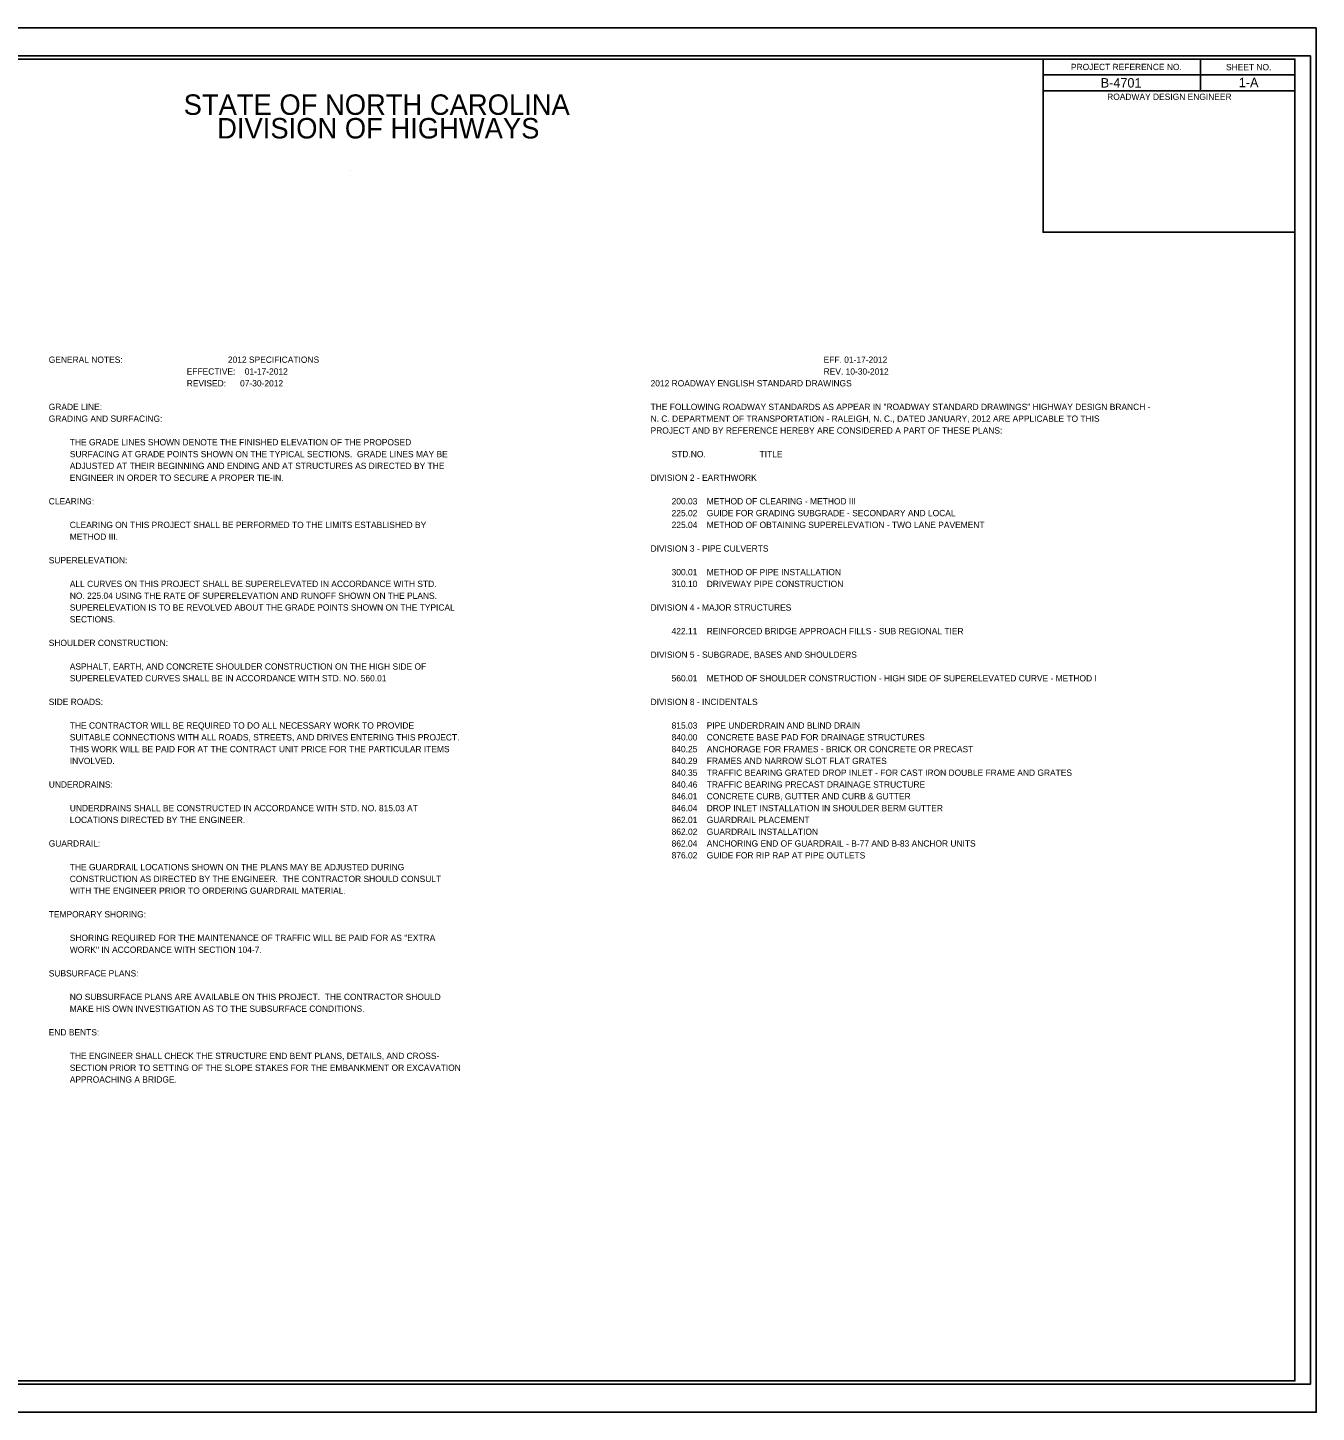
# Model space of a CAD drawing. Extents: x 573885.1 to 573944.9, y -53259.7 to -53181.6.
# Drawn here: x 573916.45 to 573936.92, y -53203.6 to -53181.6 of the extents above; entities that cross this region are included whole.
import ezdxf

# ---------------------------------------------------------------- set-up
doc = ezdxf.new("R2010")
doc.units = 0
for name, color, linetype in [('Default', 7, 'Continuous'), ('Sheet Border Standard 30in CELL', 7, 'Continuous'), ('Sheet Cutting Line CELL', 7, 'Continuous'), ('Sheet Data Field CELL', 7, 'Continuous'), ('Sheet Plot Border Inside CELL', 7, 'Continuous'), ('Sheet Plot Border Outside CELL', 7, 'Continuous'), ('Sheet Summary CELL', 7, 'Continuous')]:
    doc.layers.add(name, color=color, linetype=linetype)

msp = doc.modelspace()

# ---------------------------------------------------------------- linework, layer by layer
at = {"layer": 'Sheet Border Standard 30in CELL'}
msp.add_line((573936.579, -53182.604), (573936.579, -53184.853), dxfattribs=at)
msp.add_lwpolyline([(573932.578, -53182.604), (573936.579, -53182.604), (573936.579, -53184.854), (573932.578, -53184.854)], close=True, dxfattribs=at)
at = {"layer": 'Sheet Cutting Line CELL'}
for p, q in [((573936.919, -53181.603), (573903.239, -53181.603)), ((573903.239, -53203.603), (573936.919, -53203.603))]:
    msp.add_line(p, q, dxfattribs=at)
at = {"layer": 'Sheet Plot Border Inside CELL'}
msp.add_lwpolyline([(573936.829, -53182.052), (573903.499, -53182.052), (573903.499, -53203.154), (573936.829, -53203.154)], close=True, dxfattribs=at)
at = {"layer": 'Sheet Plot Border Outside CELL'}
msp.add_lwpolyline([(573936.919, -53181.603), (573903.239, -53181.603), (573903.239, -53203.603), (573936.919, -53203.603)], close=True, dxfattribs=at)
at = {"layer": 'Sheet Summary CELL'}
for p, q in [((573935.079, -53182.104), (573935.079, -53182.604)), ((573932.578, -53182.354), (573936.579, -53182.354)), ((573932.578, -53182.604), (573936.579, -53182.604)), ((573921.571, -53183.879), (573921.571, -53183.879))]:
    msp.add_line(p, q, dxfattribs=at)
for points in [[(573936.579, -53182.103), (573906.579, -53182.103), (573906.579, -53203.103), (573936.579, -53203.103)], [(573932.578, -53182.103), (573936.579, -53182.103), (573936.579, -53182.604), (573932.578, -53182.604)]]:
    msp.add_lwpolyline(points, close=True, dxfattribs=at)

# ---------------------------------------------------------------- texts
at = {"layer": 'Default'}
for s, p in [('GENERAL NOTES:                                             2012 SPECIFICATIONS', (573916.784, -53186.928)), ('                                                                          EFF. 01-17-2012', (573926.344, -53186.928)), ('                                                           EFFECTIVE:    01-17-2012', (573916.784, -53187.115)), ('                                                                          REV. 10-30-2012', (573926.344, -53187.115)), ('                                                           REVISED:      07-30-2012', (573916.784, -53187.303)), ('2012 ROADWAY ENGLISH STANDARD DRAWINGS', (573926.344, -53187.303)), ('GRADE LINE:  ', (573916.784, -53187.678)), ('THE FOLLOWING ROADWAY STANDARDS AS APPEAR IN "ROADWAY STANDARD DRAWINGS" HIGHWAY DESIGN BRANCH -', (573926.344, -53187.678)), ('GRADING AND SURFACING:  ', (573916.784, -53187.865)), ('N. C. DEPARTMENT OF TRANSPORTATION - RALEIGH, N. C., DATED JANUARY, 2012 ARE APPLICABLE TO THIS', (573926.344, -53187.865)), ('PROJECT AND BY REFERENCE HEREBY ARE CONSIDERED A PART OF THESE PLANS:', (573926.344, -53188.053)), ('         THE GRADE LINES SHOWN DENOTE THE FINISHED ELEVATION OF THE PROPOSED ', (573916.784, -53188.24)), ('         ADJUSTED AT THEIR BEGINNING AND ENDING AND AT STRUCTURES AS DIRECTED BY THE ', (573916.784, -53188.615)), ('         SURFACING AT GRADE POINTS SHOWN ON THE TYPICAL SECTIONS.  GRADE LINES MAY BE ', (573916.784, -53188.428)), ('         STD.NO.                       TITLE', (573926.344, -53188.428)), ('         ENGINEER IN ORDER TO SECURE A PROPER TIE-IN.  ', (573916.784, -53188.803)), ('DIVISION 2 - EARTHWORK', (573926.344, -53188.803)), ('CLEARING:  ', (573916.784, -53189.178)), ('         200.03    METHOD OF CLEARING - METHOD III', (573926.344, -53189.178)), ('         225.02    GUIDE FOR GRADING SUBGRADE - SECONDARY AND LOCAL', (573926.344, -53189.365)), ('         CLEARING ON THIS PROJECT SHALL BE PERFORMED TO THE LIMITS ESTABLISHED BY ', (573916.784, -53189.553)), ('         225.04    METHOD OF OBTAINING SUPERELEVATION - TWO LANE PAVEMENT', (573926.344, -53189.553)), ('         METHOD III.', (573916.784, -53189.74)), ('DIVISION 3 - PIPE CULVERTS', (573926.344, -53189.928)), ('SUPERELEVATION:  ', (573916.784, -53190.115)), ('         300.01    METHOD OF PIPE INSTALLATION ', (573926.344, -53190.303)), ('         ALL CURVES ON THIS PROJECT SHALL BE SUPERELEVATED IN ACCORDANCE WITH STD. ', (573916.784, -53190.49)), ('         310.10    DRIVEWAY PIPE CONSTRUCTION', (573926.344, -53190.49)), ('         NO. 225.04 USING THE RATE OF SUPERELEVATION AND RUNOFF SHOWN ON THE PLANS.', (573916.784, -53190.678)), ('         SUPERELEVATION IS TO BE REVOLVED ABOUT THE GRADE POINTS SHOWN ON THE TYPICAL ', (573916.784, -53190.865)), ('DIVISION 4 - MAJOR STRUCTURES', (573926.344, -53190.865)), ('         SECTIONS.  ', (573916.784, -53191.053)), ('         422.11    REINFORCED BRIDGE APPROACH FILLS - SUB REGIONAL TIER', (573926.344, -53191.24)), ('SHOULDER CONSTRUCTION:  ', (573916.784, -53191.428)), ('DIVISION 5 - SUBGRADE, BASES AND SHOULDERS', (573926.344, -53191.615)), ('         ASPHALT, EARTH, AND CONCRETE SHOULDER CONSTRUCTION ON THE HIGH SIDE OF', (573916.784, -53191.803)), ('         SUPERELEVATED CURVES SHALL BE IN ACCORDANCE WITH STD. NO. 560.01', (573916.784, -53191.99)), ('         560.01    METHOD OF SHOULDER CONSTRUCTION - HIGH SIDE OF SUPERELEVATED CURVE - METHOD I', (573926.344, -53191.99)), ('SIDE ROADS:  ', (573916.784, -53192.365)), ('DIVISION 8 - INCIDENTALS', (573926.344, -53192.365)), ('         THE CONTRACTOR WILL BE REQUIRED TO DO ALL NECESSARY WORK TO PROVIDE ', (573916.784, -53192.74)), ('         815.03    PIPE UNDERDRAIN AND BLIND DRAIN', (573926.344, -53192.74)), ('         SUITABLE CONNECTIONS WITH ALL ROADS, STREETS, AND DRIVES ENTERING THIS PROJECT.  ', (573916.784, -53192.928)), ('         840.00    CONCRETE BASE PAD FOR DRAINAGE STRUCTURES', (573926.344, -53192.928)), ('         THIS WORK WILL BE PAID FOR AT THE CONTRACT UNIT PRICE FOR THE PARTICULAR ITEMS ', (573916.784, -53193.115)), ('         840.25    ANCHORAGE FOR FRAMES - BRICK OR CONCRETE OR PRECAST', (573926.344, -53193.115)), ('         INVOLVED.  ', (573916.784, -53193.303)), ('         840.29    FRAMES AND NARROW SLOT FLAT GRATES', (573926.344, -53193.303)), ('UNDERDRAINS:  ', (573916.784, -53193.678)), ('         840.35    TRAFFIC BEARING GRATED DROP INLET - FOR CAST IRON DOUBLE FRAME AND GRATES', (573926.344, -53193.49)), ('         840.46    TRAFFIC BEARING PRECAST DRAINAGE STRUCTURE', (573926.344, -53193.678)), ('         846.01    CONCRETE CURB, GUTTER AND CURB & GUTTER', (573926.344, -53193.865)), ('         UNDERDRAINS SHALL BE CONSTRUCTED IN ACCORDANCE WITH STD. NO. 815.03 AT ', (573916.784, -53194.053)), ('         846.04    DROP INLET INSTALLATION IN SHOULDER BERM GUTTER', (573926.344, -53194.053)), ('         LOCATIONS DIRECTED BY THE ENGINEER.  ', (573916.784, -53194.24)), ('         862.01    GUARDRAIL PLACEMENT', (573926.344, -53194.24)), ('         862.02    GUARDRAIL INSTALLATION', (573926.344, -53194.428)), ('GUARDRAIL:  ', (573916.784, -53194.615)), ('         862.04    ANCHORING END OF GUARDRAIL - B-77 AND B-83 ANCHOR UNITS', (573926.344, -53194.615)), ('         THE GUARDRAIL LOCATIONS SHOWN ON THE PLANS MAY BE ADJUSTED DURING ', (573916.784, -53194.99)), ('         876.02    GUIDE FOR RIP RAP AT PIPE OUTLETS', (573926.344, -53194.803)), ('         CONSTRUCTION AS DIRECTED BY THE ENGINEER.  THE CONTRACTOR SHOULD CONSULT', (573916.784, -53195.178)), ('         WITH THE ENGINEER PRIOR TO ORDERING GUARDRAIL MATERIAL.', (573916.784, -53195.365)), ('TEMPORARY SHORING:  ', (573916.784, -53195.74)), ('         WORK" IN ACCORDANCE WITH SECTION 104-7.  ', (573916.784, -53196.303)), ('         SHORING REQUIRED FOR THE MAINTENANCE OF TRAFFIC WILL BE PAID FOR AS "EXTRA ', (573916.784, -53196.115)), ('SUBSURFACE PLANS:  ', (573916.784, -53196.678)), ('         NO SUBSURFACE PLANS ARE AVAILABLE ON THIS PROJECT.  THE CONTRACTOR SHOULD ', (573916.784, -53197.053)), ('         MAKE HIS OWN INVESTIGATION AS TO THE SUBSURFACE CONDITIONS.  ', (573916.784, -53197.24)), ('END BENTS:  ', (573916.784, -53197.615)), ('         THE ENGINEER SHALL CHECK THE STRUCTURE END BENT PLANS, DETAILS, AND CROSS-', (573916.784, -53197.99)), ('         SECTION PRIOR TO SETTING OF THE SLOPE STAKES FOR THE EMBANKMENT OR EXCAVATION ', (573916.784, -53198.178)), ('         APPROACHING A BRIDGE.  ', (573916.784, -53198.365))]:
    msp.add_text(s, height=0.1, dxfattribs=at).set_placement(p)
at = {"layer": 'Sheet Border Standard 30in CELL'}
msp.add_text('ROADWAY DESIGN ENGINEER', height=0.1, dxfattribs=at).set_placement((573933.597, -53182.75))
at = {"layer": 'Sheet Data Field CELL'}
for s, p in [('B-4701', (573933.495, -53182.554)), ('1-A', (573935.688, -53182.548))]:
    msp.add_text(s, height=0.15, dxfattribs=at).set_placement(p)
at = {"layer": 'Sheet Summary CELL'}
for s, height, p in [('PROJECT REFERENCE NO.', 0.1, (573933.022, -53182.277)), ('SHEET NO.', 0.1, (573935.485, -53182.279)), ('STATE OF NORTH CAROLINA', 0.325, (573918.927, -53182.988)), ('DIVISION OF HIGHWAYS', 0.325, (573919.459, -53183.363))]:
    msp.add_text(s, height=height, dxfattribs=at).set_placement(p)

doc.saveas('drawing.dxf')
